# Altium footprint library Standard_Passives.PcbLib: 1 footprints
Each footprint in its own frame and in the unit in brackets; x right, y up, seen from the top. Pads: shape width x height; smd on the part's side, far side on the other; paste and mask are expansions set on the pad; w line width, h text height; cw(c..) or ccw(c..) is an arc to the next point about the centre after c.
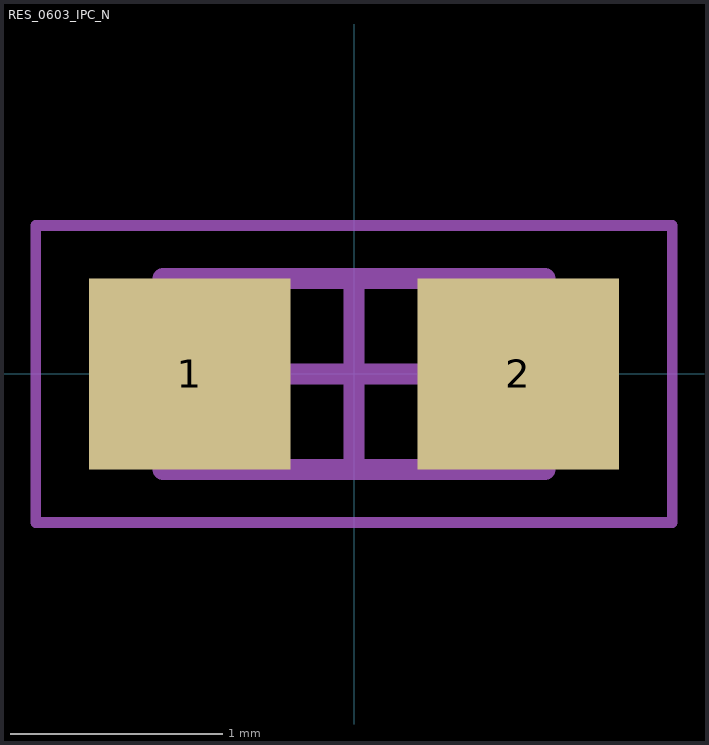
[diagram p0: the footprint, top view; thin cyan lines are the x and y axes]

## RES_0603_IPC_N [mm] "Chip Resistor, 2-Leads, Body 1.60x0.80mm, IPC Nominal Density"
height 0.55
pads (2):
  rect 0.95x0.9 smd: 1(-0.775,0) 2(0.775,0)
Mechanical 13:
  lines w0.1: -0.9,-0.45 -0.9,0.45 0.9,0.45 0.9,-0.45 -0.9,-0.45
Mechanical 15:
  lines w0.05: -1.5,-0.7 -1.5,0.7 1.5,0.7 1.5,-0.7 -1.5,-0.7
  lines w0.1: -0.45,0 0.45,0 ; 0,-0.45 0,0.45
3D body "RES_0603_IPC_N.step": height 0.55, standoff 0, extent -0.9,-0.45 0.9,0.45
